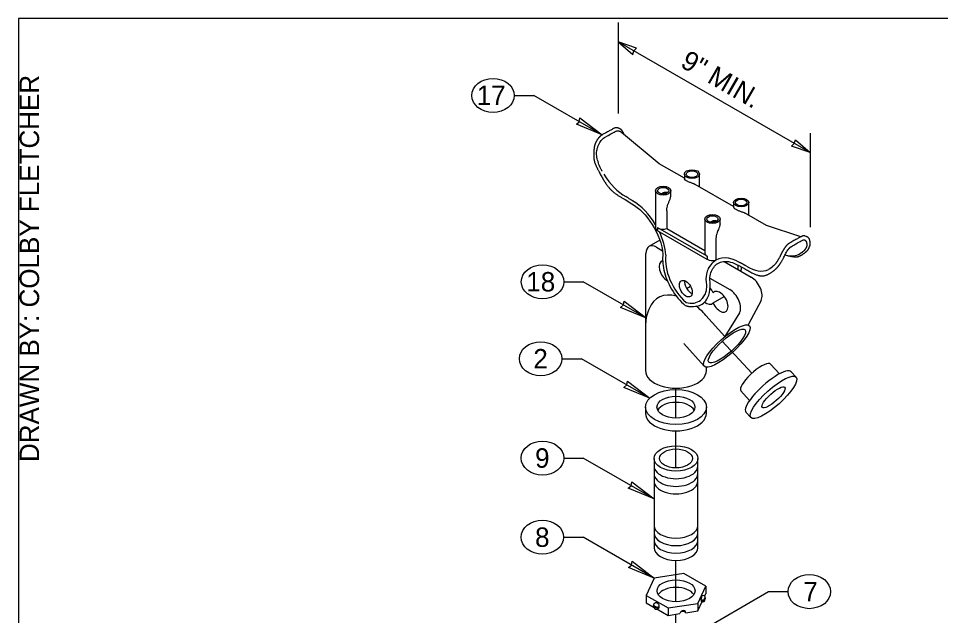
# Model space of a CAD drawing. Extents: x 99862 to 104211, y 98939 to 105076.
# Drawn here: x 99862 to 100620, y 104584 to 105076 of the extents above; entities that cross this region are included whole.
import ezdxf

# ---------------------------------------------------------------- set-up
doc = ezdxf.new("R2010")
doc.units = 0
for name, color, linetype in [('Level 1', 7, 'Continuous'), ('Level 15', 7, 'Continuous'), ('Level 17', 7, 'Continuous'), ('Level 18', 7, 'Continuous'), ('Level 2', 7, 'Continuous'), ('Level 20', 7, 'Continuous'), ('Level 62', 7, 'Continuous'), ('Level 8', 7, 'Continuous'), ('Level 9', 7, 'Continuous')]:
    doc.layers.add(name, color=color, linetype=linetype)

msp = doc.modelspace()

# ---------------------------------------------------------------- linework, layer by layer
at = {"layer": 'Level 1'}
msp.add_lwpolyline([(99862, 102999.5), (103151, 102999.5), (103151, 105075.5), (99862, 105075.5)], close=True, dxfattribs=at)
at = {"layer": 'Level 15'}
for p, q in [((100355.28, 105072.22), (100355.28, 104997.29)), ((100513.12, 104965.09), (100355.28, 105056.22)), ((100269.85, 105012.13), (100285.85, 105012.13)), ((100342.14, 104979.63), (100285.85, 105012.13)), ((100513.12, 104981.09), (100513.12, 104903.67)), ((100310.59, 104858.79), (100326.59, 104858.79)), ((100378.53, 104828.8), (100326.59, 104858.79)), ((100465.33, 104783.53), (100440.92, 104809.97)), ((100309, 104795.46), (100325, 104795.46)), ((100381.27, 104762.98), (100325, 104795.46)), ((100402.8, 104746.63), (100402.8, 104771.21)), ((100402.8, 104705.63), (100402.8, 104736.11)), ((100310.54, 104713.74), (100326.54, 104713.74)), ((100384.8, 104680.1), (100326.54, 104713.74)), ((100310.42, 104648.62), (100326.42, 104648.62)), ((100384.96, 104614.83), (100326.42, 104648.62)), ((100402.8, 104595.47), (100402.8, 104629.55)), ((100420.5, 104570.03), (100478.97, 104603.78)), ((100478.97, 104603.78), (100494.97, 104603.78)), ((100402.8, 104550.76), (100402.8, 104585.18))]:
    msp.add_line(p, q, dxfattribs=at)
for points in [[(100355.28, 105056.22), (100367.35, 105045.69), (100368.26, 105048.72), (100370.44, 105051.03)], [(100342.14, 104979.63), (100320.88, 104988.46), (100323.28, 104990.52), (100323.86, 104993.63)], [(100513.12, 104965.09), (100497.96, 104970.28), (100500.13, 104972.59), (100501.04, 104975.62)], [(100378.53, 104828.8), (100357.27, 104837.63), (100359.68, 104839.69), (100360.25, 104842.8)], [(100381.27, 104762.98), (100360.01, 104771.81), (100362.41, 104773.87), (100362.99, 104776.98)], [(100384.8, 104680.1), (100363.54, 104688.93), (100365.95, 104690.99), (100366.53, 104694.1)], [(100384.96, 104614.83), (100363.69, 104623.66), (100366.1, 104625.71), (100366.68, 104628.83)]]:
    msp.add_lwpolyline(points, close=True, dxfattribs=at)
at = {"layer": 'Level 17'}
for p, q in [((100389.03, 104955.9), (100358.02, 104981.76)), ((100409.73, 104943.95), (100389.03, 104955.9)), ((100409.73, 104947.4), (100409.73, 104943.54)), ((100422.23, 104936.73), (100422.23, 104947.4)), ((100450.16, 104920.61), (100418.66, 104938.8)), ((100386.11, 104933.76), (100386.11, 104903.14)), ((100398.61, 104929.9), (100398.61, 104933.76)), ((100361, 104926.39), (100366.5, 104922.98)), ((100450.16, 104924.06), (100450.16, 104920.2)), ((100462.66, 104913.39), (100462.66, 104924.06)), ((100395.31, 104917.1), (100395.31, 104902.51)), ((100477.17, 104905.01), (100459.08, 104915.46)), ((100426.53, 104910.43), (100426.53, 104882.36)), ((100439.03, 104906.57), (100439.03, 104910.43)), ((100387.56, 104903.36), (100387.58, 104903.37)), ((100387.56, 104903.36), (100387.56, 104900.81)), ((100387.94, 104903.14), (100387.56, 104903.36)), ((100428.36, 104877.25), (100387.56, 104900.81)), ((100387.58, 104903.37), (100387.58, 104900.82)), ((100428.36, 104879.81), (100387.94, 104903.14)), ((100395.31, 104902.51), (100426.53, 104884.49)), ((100505.57, 104895.9), (100477.17, 104905.01)), ((100435.73, 104893.77), (100435.73, 104876.62)), ((100428.36, 104879.81), (100428.36, 104877.25)), ((100454.56, 104872.14), (100460.07, 104869.19))]:
    msp.add_line(p, q, dxfattribs=at)
for centre, major_axis, ratio, start_param, end_param in [((100360.9, 104958.79), (-17.72, 31.29), 0.57735, 1.6138, 2.395219), ((100367.06, 104893.64), (-19.52, 33.81), 0.57735, 4.736377, 5.49473), ((100392.36, 104903.14), (-6.25, 0), 0.57735, 6.283185, 6.98269), ((100392.36, 104905.7), (-6.25, 0), 0.57735, 0.699505, 0.785398), ((100392.36, 104905.7), (-6.25, 0), 0.57735, 0.785398, 2.061945), ((100367.06, 104893.64), (-19.52, 33.81), 0.57735, 4.022982, 4.565814), ((100416.66, 104863.68), (-15.86, 27.48), 0.57735, 0.616549, 2.107388), ((100432.78, 104882.36), (-6.25, 0), 0.57735, 6.283185, 7.068583), ((100432.78, 104879.81), (6.25, 0), 0.57735, 3.926991, 5.203538), ((100455.21, 104842.75), (-19.52, 33.81), 0.57735, 5.500844, 6.398051), ((100485.92, 104914.3), (-18.75, 32.48), 0.577329, 2.604955, 3.160056), ((100430.52, 104884.44), (-16.61, 28.77), 0.57735, 3.833891, 3.985022), ((100461.7, 104900.45), (-17.98, 31.14), 0.57735, 2.31717, 3.098589), ((100415.23, 104855.62), (3.75, -6.5), 0.57735, 3.754385, 5.670393), ((100405.61, 104870.06), (15.86, -27.48), 0.57735, 5.746594, 6.3945)]:
    msp.add_ellipse(centre, major_axis=major_axis, ratio=ratio, start_param=start_param, end_param=end_param, dxfattribs=at)
for centre, major_axis in [((100415.98, 104947.4), (-6.25, 0)), ((100415.98, 104947.4), (-4.69, 0)), ((100392.36, 104933.76), (-6.25, 0)), ((100392.36, 104933.76), (4.69, 0)), ((100456.41, 104924.06), (6.25, 0)), ((100456.41, 104924.06), (4.69, 0)), ((100432.78, 104910.43), (6.25, 0)), ((100432.78, 104910.43), (-4.69, 0)), ((100410.92, 104853.13), (3.75, -6.5))]:
    msp.add_ellipse(centre, major_axis=major_axis, ratio=0.57735, dxfattribs=at)
for points, degree in [([(100355.28, 104985.29), (100353.79, 104985.71), (100352.14, 104985.37), (100342.14, 104979.63)], 2), ([(100344.01, 104977.38), (100353.03, 104982.58), (100353.63, 104982.8), (100354.76, 104983.01), (100355.29, 104983.01), (100355.79, 104982.91)], 3), ([(100360.03, 104980.49), (100358.96, 104982.69), (100357.41, 104984.38), (100355.28, 104985.29)], 2), ([(100355.79, 104982.91), (100356.62, 104982.73), (100357.35, 104982.32), (100358.02, 104981.76)], 2), ([(100338.09, 104975.67), (100336.55, 104973.11), (100335.58, 104970.17), (100335.33, 104967.29)], 2), ([(100342.14, 104979.63), (100340.7, 104978.77), (100339.32, 104977.43), (100338.09, 104975.67)], 2), ([(100340.68, 104974.19), (100341.17, 104974.86), (100341.7, 104975.48), (100342.82, 104976.56), (100343.42, 104977.03), (100344.01, 104977.38)], 3), ([(100335.33, 104967.29), (100334.89, 104961.44), (100336.2, 104955.45), (100339.05, 104950.27)], 2), ([(100337.74, 104966.87), (100338.01, 104968.15), (100338.37, 104969.43), (100339.33, 104971.91), (100339.94, 104973.1), (100340.68, 104974.19)], 3), ([(100341.3, 104951.29), (100340.02, 104953.7), (100339, 104956.23), (100337.7, 104961.46), (100337.41, 104964.17), (100337.74, 104966.87)], 3), ([(100339.06, 104950.24), (100344.36, 104939.89), (100352.63, 104930.86), (100361, 104926.39)], 2), ([(100342.13, 104949.77), (100341.84, 104950.27), (100341.56, 104950.78), (100341.3, 104951.29)], 2), ([(100418.67, 104938.79), (100418.43, 104938.93), (100418.17, 104939.06), (100417.28, 104939.47), (100416.57, 104939.73), (100415.09, 104940.25), (100414.3, 104940.52), (100412.84, 104941.09), (100412.15, 104941.41), (100411, 104942.07), (100410.54, 104942.41), (100409.92, 104943.04), (100409.76, 104943.32), (100409.73, 104943.52), (100409.73, 104943.53), (100409.73, 104943.54)], 3), ([(100395.76, 104931.9), (100395.74, 104931.92), (100395.71, 104931.93), (100395.19, 104932.23), (100394.58, 104932.38), (100393.31, 104932.35), (100392.66, 104932.17), (100391.71, 104931.66), (100391.38, 104931.43), (100391.07, 104931.16)], 3), ([(100395.31, 104917.1), (100395.24, 104918.52), (100395.43, 104919.88), (100396.04, 104921.99), (100396.3, 104922.69), (100396.87, 104924.14), (100397.18, 104924.89), (100397.78, 104926.38), (100398.06, 104927.14), (100398.47, 104928.59), (100398.6, 104929.28), (100398.61, 104929.92)], 3), ([(100367.15, 104925.47), (100366.43, 104925.91), (100365.71, 104926.36), (100364.99, 104926.8), (100363.88, 104927.49), (100362.76, 104928.19), (100361.64, 104928.88)], 3), ([(100366.54, 104922.96), (100372.17, 104919.7), (100384.76, 104907.33), (100391.4, 104889.67), (100392.07, 104881.37)], 3), ([(100450.16, 104920.2), (100450.16, 104920.19), (100450.16, 104920.18), (100450.18, 104919.99), (100450.33, 104919.72), (100450.95, 104919.09), (100451.4, 104918.75), (100452.55, 104918.08), (100453.23, 104917.77), (100454.7, 104917.19), (100455.48, 104916.92), (100456.97, 104916.4), (100457.68, 104916.14), (100458.59, 104915.73), (100458.85, 104915.59), (100459.1, 104915.45)], 3), ([(100436.18, 104908.56), (100436.16, 104908.58), (100436.13, 104908.6), (100435.61, 104908.9), (100435, 104909.04), (100433.73, 104909.01), (100433.07, 104908.83), (100432.13, 104908.32), (100431.8, 104908.09), (100431.5, 104907.82)], 3), ([(100439.03, 104906.54), (100439.02, 104905.92), (100438.89, 104905.25), (100438.49, 104903.82), (100438.21, 104903.06), (100437.31, 104900.82), (100436.68, 104899.37), (100436.06, 104897.25), (100435.91, 104896.56), (100435.73, 104895.21), (100435.72, 104894.55), (100435.73, 104893.77)], 3), ([(100509.44, 104896.28), (100507.95, 104896.7), (100506.31, 104896.36), (100496.26, 104890.6)], 2), ([(100497.85, 104887.91), (100506.82, 104893.06), (100508, 104893.4), (100508.5, 104893.3)], 2), ([(100508.5, 104893.3), (100508.71, 104893.21), (100508.89, 104893.1), (100509.05, 104892.98)], 2), ([(100509.05, 104892.98), (100509.72, 104892.44), (100510.13, 104891.68), (100510.23, 104890.79)], 2), ([(100513.12, 104891.67), (100512.84, 104893.71), (100511.53, 104895.44), (100509.64, 104896.21)], 2), ([(100512.47, 104887.04), (100512.59, 104887.32), (100513.15, 104888.69), (100513.32, 104890.34), (100513.12, 104891.67)], 3), ([(100492.31, 104886.76), (100490.75, 104884.42), (100489.39, 104881.91), (100488.41, 104879.6)], 2), ([(100491.26, 104878.32), (100491.69, 104879.34), (100492.73, 104881.53), (100494.13, 104883.86), (100494.92, 104885.03)], 3), ([(100496.3, 104890.62), (100494.86, 104889.76), (100493.48, 104888.42), (100492.36, 104886.83)], 2), ([(100494.92, 104885.03), (100495.79, 104886.28), (100496.86, 104887.31), (100497.88, 104887.93)], 2), ([(100509.29, 104885.9), (100508.73, 104884.97), (100507.95, 104884.11), (100506.96, 104883.32)], 2), ([(100508.99, 104882.83), (100510.57, 104884.05), (100511.76, 104885.45), (100512.47, 104887.04)], 2), ([(100510.24, 104890.69), (100510.5, 104889.05), (100510.19, 104887.4), (100509.29, 104885.9)], 2), ([(100392.07, 104881.37), (100391.62, 104878.12), (100391.94, 104868.66), (100398.21, 104852.51), (100406.4, 104842.75), (100410.45, 104839.31)], 3), ([(100488.41, 104879.6), (100486.02, 104875.37), (100483.42, 104872.08), (100480.55, 104869.86)], 2), ([(100483.17, 104867.92), (100485.87, 104870.06), (100488.63, 104873.64), (100491.19, 104878.18)], 2), ([(100494.6, 104880.36), (100500.07, 104879.04), (100505.2, 104879.79), (100508.98, 104882.82)], 2), ([(100506.96, 104883.32), (100506.35, 104882.83), (100505.7, 104882.4), (100505.02, 104882.03)], 2), ([(100433.58, 104875.05), (100433.42, 104874.9), (100430.02, 104871.84), (100427.9, 104866.82), (100427.43, 104861.16)], 3), ([(100430.55, 104860.96), (100430.87, 104864.66), (100433.11, 104871.4), (100440.86, 104876.79), (100449.54, 104875.02), (100454.52, 104872.16)], 3), ([(100460.63, 104871.73), (100458.79, 104872.71), (100456.96, 104873.69), (100455.12, 104874.68)], 2), ([(100456.31, 104867.02), (100456.51, 104868.3), (100456.63, 104869.64), (100456.65, 104871.02)], 2), ([(100460.02, 104869.22), (100468.47, 104863.96), (100477.37, 104863.28), (100483.15, 104867.91)], 2), ([(100480.55, 104869.86), (100480.04, 104869.52), (100479.55, 104869.24), (100479.08, 104869.02)], 2), ([(100414.21, 104838.43), (100414.69, 104838.39), (100418.21, 104838.06), (100428.17, 104840.69), (100431.63, 104852.01), (100430.55, 104860.96)], 3), ([(100427.44, 104861.01), (100428.44, 104853.62), (100426.85, 104847.16), (100423.25, 104843.86), (100423.14, 104843.77)], 3), ([(100410.64, 104839.21), (100411.83, 104838.84), (100412.99, 104838.59), (100414.19, 104838.44)], 2)]:
    msp.add_open_spline(points, degree=degree, dxfattribs=at)
at = {"layer": 'Level 18'}
for p, q in [((100389.55, 104892.92), (100380.62, 104887.77)), ((100386.87, 104887.15), (100391.71, 104884.35)), ((100378.03, 104825.16), (100378.03, 104882.05)), ((100442.49, 104875.45), (100464.76, 104862.59)), ((100430.65, 104861.88), (100447.08, 104852.39)), ((100411.56, 104853.31), (100414.75, 104855.15)), ((100433.4, 104841.53), (100442.53, 104846.8)), ((100472.76, 104843.44), (100462.06, 104823.24)), ((100443.06, 104813.63), (100427.38, 104831.17)), ((100455.08, 104833.23), (100443.08, 104813.64)), ((100377.8, 104820.62), (100377.8, 104785.64)), ((100409.35, 104807.91), (100426.06, 104789.22)), ((100427.8, 104785.64), (100427.8, 104788.45)), ((100480.65, 104791.11), (100487.88, 104783.02)), ((100501.66, 104780.3), (100497.66, 104784.78)), ((100456.26, 104769.17), (100463.38, 104761.2)), ((100460.39, 104751.45), (100464.39, 104746.97))]:
    msp.add_line(p, q, dxfattribs=at)
for centre, major_axis, ratio, start_param, end_param in [((100386.87, 104876.94), (-6.25, 10.83), 0.57735, 5.497787, 7.068583), ((100395.57, 104867.41), (-4.69, 8.12), 0.57735, 6.096751, 8.673199), ((100464.76, 104852.39), (6.25, -10.83), 0.57735, 0.347397, 2.356194), ((100427.77, 104848.82), (-4.69, 8.12), 0.57735, 4.483455, 5.043844), ((100411.64, 104805.31), (-23.33, 40.4), 0.57735, 5.757457, 6.704874), ((100439.03, 104842.32), (-4.69, 8.12), 0.57735, 1.341862, 6.512119), ((100447.08, 104842.18), (6.25, -10.83), 0.57735, 0.347397, 2.356194), ((100413.39, 104804.75), (-23.33, 40.4), 0.57735, 5.059786, 5.311504), ((100427.77, 104848.82), (-4.69, 8.12), 0.57735, 2.096305, 3.370527), ((100402.8, 104785.64), (-25, 0), 0.57735, 6.283185, 9.424778), ((100468.42, 104780.18), (12.23, 10.94), 0.277977, 0.174514, 3.16344), ((100479.02, 104768.11), (18.63, 16.67), 0.277977, 6.283185, 9.424778), ((100468.42, 104780.18), (12.23, 10.94), 0.277977, 6.283183, 6.457699)]:
    msp.add_ellipse(centre, major_axis=major_axis, ratio=ratio, start_param=start_param, end_param=end_param, dxfattribs=at)
for centre, major_axis in [((100444.7, 104805.88), (-18.63, -16.67)), ((100444.7, 104805.88), (-14.91, -13.33)), ((100483.03, 104763.64), (18.63, 16.67)), ((100483.03, 104763.64), (9.28, 8.3))]:
    msp.add_ellipse(centre, major_axis=major_axis, ratio=0.277977, dxfattribs=at)
msp.add_open_spline([(100380.82, 104836.69), (100378.75, 104831.62), (100377.8, 104826.15), (100377.8, 104820.62)], degree=2, dxfattribs=at)
at = {"layer": 'Level 2'}
for p, q in [((100377.8, 104755.65), (100377.8, 104750.55)), ((100427.8, 104750.55), (100427.8, 104755.65))]:
    msp.add_line(p, q, dxfattribs=at)
for major_axis in [(25, 0), (15.62, 0)]:
    msp.add_ellipse((100402.8, 104755.65), major_axis=major_axis, ratio=0.57735, dxfattribs=at)
for major_axis, start_param, end_param in [((-15.62, 0), 3.428349, 5.996429), ((-25, 0), 6.283185, 9.424778)]:
    msp.add_ellipse((100402.8, 104750.55), major_axis=major_axis, ratio=0.57735, start_param=start_param, end_param=end_param, dxfattribs=at)
at = {"layer": 'Level 20'}
for centre in [(100252.35, 105012.13), (100293.09, 104858.79), (100291.5, 104795.46), (100293.04, 104713.74), (100292.92, 104648.62), (100512.47, 104603.78)]:
    msp.add_ellipse(centre, major_axis=(-17.5, 0), ratio=0.8, dxfattribs=at)
at = {"layer": 'Level 8'}
for p, q in [((100409.41, 104618.61), (100384.96, 104614.83)), ((100427.31, 104608.28), (100409.41, 104618.61)), ((100384.96, 104614.83), (100378.41, 104600.71)), ((100420.75, 104594.16), (100427.31, 104608.28)), ((100427.31, 104608.28), (100427.31, 104602.08)), ((100378.41, 104600.71), (100378.41, 104594.51)), ((100378.41, 104600.71), (100396.3, 104590.38)), ((100420.75, 104587.96), (100424.28, 104595.55)), ((100423.65, 104595.65), (100424.98, 104595.44)), ((100424.72, 104596.86), (100423.87, 104596.99)), ((100423.87, 104596.34), (100424.16, 104596.95)), ((100424.72, 104596.21), (100423.87, 104596.34)), ((100425.75, 104600.38), (100424.41, 104600.59)), ((100426.1, 104597.33), (100426.79, 104598.81)), ((100426.79, 104598.15), (100426.1, 104596.68)), ((100426.38, 104600.07), (100427.31, 104602.08)), ((100378.41, 104594.51), (100384.81, 104590.81)), ((100384.65, 104592.29), (100386.52, 104591.21)), ((100386.52, 104590.56), (100384.65, 104591.64)), ((100386.1, 104594.61), (100385.13, 104594.05)), ((100387.05, 104589.52), (100396.3, 104584.18)), ((100387.63, 104589.72), (100388.6, 104590.28)), ((100388.12, 104591.2), (100388.75, 104591.56)), ((100388.12, 104590.55), (100388.75, 104590.91)), ((100388.18, 104591.23), (100388.75, 104590.91)), ((100396.3, 104590.38), (100420.75, 104594.16)), ((100396.3, 104590.38), (100396.3, 104584.18)), ((100410.94, 104586.44), (100420.75, 104587.96)), ((100420.75, 104594.16), (100420.75, 104587.96)), ((100396.3, 104584.18), (100406.11, 104585.69))]:
    msp.add_line(p, q, dxfattribs=at)
msp.add_ellipse((100402.86, 104604.49), major_axis=(15.63, 0), ratio=0.57735, dxfattribs=at)
for centre, major_axis, ratio, start_param, end_param in [((100402.86, 104598.29), (15.63, 0), 0.57735, 0.350805, 2.790788), ((100424.03, 104598.12), (0.38, 2.47), 0.211325, 0, 3.141593), ((100424.51, 104598.04), (0.38, 2.47), 0.211325, 2.04202, 2.363401), ((100387.35, 104592.44), (1.25, -2.17), 0.57735, 6.283185, 9.424778), ((100387, 104592.24), (1.25, -2.17), 0.57735, 0.624708, 0.946089), ((100408.53, 104586.07), (2.27, 1.05), 0.788675, 5.932306, 9.073899), ((100408.53, 104586.07), (2.5, 0), 0.57735, 0.261799, 2.46451)]:
    msp.add_ellipse(centre, major_axis=major_axis, ratio=ratio, start_param=start_param, end_param=end_param, dxfattribs=at)
for points, degree in [([(100424.72, 104596.86), (100425.01, 104596.82), (100425.33, 104596.84), (100425.84, 104597.02), (100426.03, 104597.17), (100426.1, 104597.33)], 3), ([(100426.1, 104596.68), (100426.03, 104596.51), (100425.84, 104596.37), (100425.33, 104596.19), (100425.01, 104596.16), (100424.72, 104596.21)], 3), ([(100424.98, 104595.44), (100425.74, 104595.37), (100426.6, 104596.3), (100426.73, 104597.57), (100426.83, 104598.3)], 3), ([(100426.83, 104599.02), (100426.82, 104599.53), (100426.47, 104600.28), (100425.75, 104600.38)], 2), ([(100426.7, 104598.63), (100426.83, 104598.48), (100426.86, 104598.31), (100426.79, 104598.15)], 2), ([(100426.79, 104598.81), (100426.82, 104598.87), (100426.83, 104598.93), (100426.83, 104599)], 2), ([(100385.13, 104594.05), (100384.68, 104593.79), (100384.39, 104593.32), (100384.31, 104592.82)], 2), ([(100384.32, 104592.82), (100384.31, 104592.8), (100384.31, 104592.77), (100384.31, 104592.58), (100384.44, 104592.41), (100384.65, 104592.29)], 3), ([(100384.65, 104591.64), (100384.44, 104591.76), (100384.31, 104591.92), (100384.31, 104592.21), (100384.36, 104592.33), (100384.46, 104592.43)], 3), ([(100384.31, 104592.05), (100384.57, 104590.5), (100386.24, 104588.92), (100387.63, 104589.72)], 2), ([(100386.52, 104591.21), (100386.73, 104591.09), (100387.02, 104591.01), (100387.62, 104591.01), (100387.91, 104591.08), (100388.12, 104591.2)], 3), ([(100388.12, 104590.55), (100387.91, 104590.43), (100387.62, 104590.36), (100387.02, 104590.36), (100386.73, 104590.44), (100386.52, 104590.56)], 3)]:
    msp.add_open_spline(points, degree=degree, dxfattribs=at)
at = {"layer": 'Level 9'}
for p, q in [((100384.8, 104713.42), (100384.8, 104639.94)), ((100420.8, 104639.94), (100420.8, 104713.42))]:
    msp.add_line(p, q, dxfattribs=at)
for major_axis in [(18, 0), (13.5, 0)]:
    msp.add_ellipse((100402.8, 104713.42), major_axis=major_axis, ratio=0.57735, dxfattribs=at)
for centre, start_param in [((100402.8, 104707.14), 3.141588), ((100402.8, 104700.82), 3.141587), ((100402.8, 104694.69), 3.141585), ((100402.8, 104658.22), 3.141593), ((100402.8, 104652.08), 3.141593), ((100402.8, 104645.95), 3.141593), ((100402.8, 104639.94), 3.141593)]:
    msp.add_ellipse(centre, major_axis=(18, 0), ratio=0.57735, start_param=start_param, end_param=6.283185, dxfattribs=at)

# ---------------------------------------------------------------- texts
at = {"layer": 'Level 20'}
for s, rotation, p in [('9" MIN.', 330.0064, (100405.54, 105036.15)), ('7', 360, (100507.55, 104595.78))]:
    msp.add_text(s, height=16, rotation=rotation, dxfattribs=at).set_placement(p)
for s, p in [('17', (100238.9, 105004.13)), ('18', (100279.71, 104850.79)), ('2', (100285.51, 104787.47)), ('9', (100286.95, 104705.75)), ('8', (100286.91, 104640.62))]:
    msp.add_text(s, height=16, dxfattribs=at).set_placement(p)
at = {"layer": 'Level 62'}
msp.add_text('DRAWN BY: COLBY FLETCHER', height=16, rotation=90, dxfattribs=at).set_placement((99879, 104710.46))

doc.saveas('drawing.dxf')
